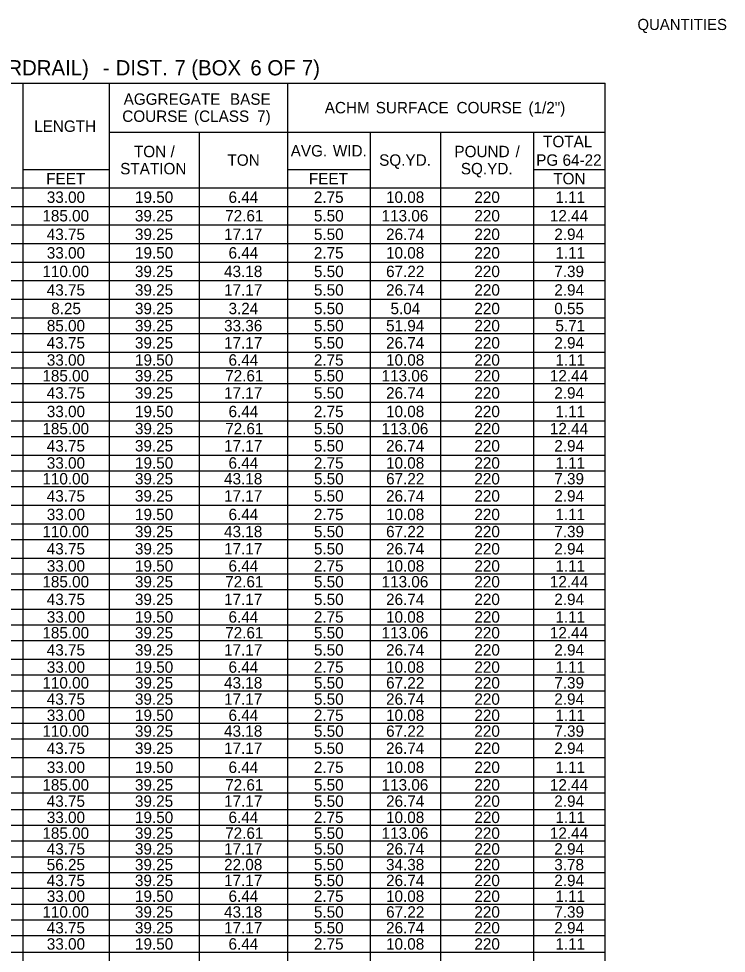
# Model space of a CAD drawing. Extents: x 544250 to 1930787, y -1948365 to 596640.
# Drawn here: x 545339.7 to 545711.4, y -1947838.8 to -1947347.7 of the extents above; entities that cross this region are included whole.
import ezdxf

# ---------------------------------------------------------------- set-up
doc = ezdxf.new("R2010")
doc.units = 0
doc.layers.add('Default', color=7, linetype='Continuous')
doc.layers.add('R_Border Prem', color=7, linetype='Continuous')

msp = doc.modelspace()

# ---------------------------------------------------------------- linework, layer by layer
at = {"layer": 'Default'}
for p, q in [((544964.76, -1947381.48), (545647.75, -1947381.48)), ((545342.09, -1948198.53), (545342.09, -1947381.48)), ((545387.43, -1948198.53), (545387.43, -1947381.48)), ((545481.03, -1948209.26), (545481.03, -1947381.48)), ((545647.75, -1948209.26), (545647.75, -1947381.48)), ((545387.43, -1947407.32), (545647.75, -1947407.32)), ((545434.71, -1948209.26), (545434.71, -1947407.32)), ((545524.41, -1947407.32), (545561.46, -1947407.32)), ((545524.41, -1948209.26), (545524.41, -1947407.32)), ((545561.46, -1948209.26), (545561.46, -1947407.32)), ((545610.21, -1948209.26), (545610.21, -1947407.32)), ((545342.09, -1947426.82), (545387.43, -1947426.82)), ((545387.43, -1947436.57), (545387.43, -1947426.82)), ((545481.03, -1947426.82), (545524.41, -1947426.82)), ((545481.03, -1947436.57), (545481.03, -1947426.82)), ((545524.41, -1947436.57), (545524.41, -1947426.82)), ((545610.21, -1947426.82), (545647.75, -1947426.82)), ((544964.76, -1947436.57), (545647.75, -1947436.57)), ((545387.43, -1947436.57), (545524.41, -1947436.57)), ((545524.41, -1947436.57), (545647.75, -1947436.57)), ((545170.98, -1947446.32), (545647.75, -1947446.32)), ((545170.98, -1947456.07), (545647.75, -1947456.07)), ((545170.98, -1947465.82), (545647.75, -1947465.82)), ((545170.98, -1947475.57), (545647.75, -1947475.57)), ((545170.98, -1947485.32), (545647.75, -1947485.32)), ((545170.98, -1947495.07), (545647.75, -1947495.07)), ((545170.98, -1947504.82), (545647.75, -1947504.82)), ((545170.98, -1947513.11), (545647.75, -1947513.11)), ((545170.98, -1947522.86), (545647.75, -1947522.86)), ((545170.98, -1947531.15), (545647.75, -1947531.15)), ((545170.98, -1947539.43), (545647.75, -1947539.43)), ((544964.76, -1947549.18), (545647.75, -1947549.18)), ((545170.98, -1947558.93), (545647.75, -1947558.93)), ((545170.98, -1947567.22), (545647.75, -1947567.22)), ((545170.98, -1947576.97), (545647.75, -1947576.97)), ((545170.98, -1947585.26), (545647.75, -1947585.26)), ((545170.98, -1947593.55), (545647.75, -1947593.55)), ((545170.98, -1947603.3), (545647.75, -1947603.3)), ((545170.98, -1947613.05), (545647.75, -1947613.05)), ((545170.98, -1947621.33), (545647.75, -1947621.33)), ((545170.98, -1947631.08), (545647.75, -1947631.08)), ((545170.98, -1947639.37), (545647.75, -1947639.37)), ((545170.98, -1947647.66), (545647.75, -1947647.66)), ((544964.76, -1947657.9), (545647.75, -1947657.9)), ((545170.98, -1947666.18), (545647.75, -1947666.18)), ((545170.98, -1947674.47), (545647.75, -1947674.47)), ((545170.98, -1947684.22), (545647.75, -1947684.22)), ((545170.98, -1947692.51), (545647.75, -1947692.51)), ((545170.98, -1947700.8), (545647.75, -1947700.8)), ((545170.98, -1947709.57), (545647.75, -1947709.57)), ((545170.98, -1947717.86), (545647.75, -1947717.86)), ((545170.98, -1947726.15), (545647.75, -1947726.15)), ((545170.98, -1947735.9), (545647.75, -1947735.9)), ((545170.98, -1947746.13), (545647.75, -1947746.13)), ((545170.98, -1947754.42), (545647.75, -1947754.42)), ((544964.76, -1947763.2), (545647.75, -1947763.2)), ((545170.98, -1947771.48), (545647.75, -1947771.48)), ((545170.98, -1947779.77), (545647.75, -1947779.77)), ((545170.98, -1947788.06), (545647.75, -1947788.06)), ((545170.98, -1947796.35), (545647.75, -1947796.35)), ((545170.98, -1947804.63), (545647.75, -1947804.63)), ((545170.98, -1947812.92), (545647.75, -1947812.92)), ((545170.98, -1947821.21), (545647.75, -1947821.21)), ((545170.98, -1947829.5), (545647.75, -1947829.5)), ((545170.98, -1947838.27), (545647.75, -1947838.27))]:
    msp.add_line(p, q, dxfattribs=at)

# ---------------------------------------------------------------- texts
for s, height, p in [(' GUARDRAIL)', 8, (545307.6, -1947377.44)), (' DIST.', 8, (545387.66, -1947377.44)), (' 7', 8, (545418.56, -1947377.44)), (' (BOX', 8, (545427.38, -1947377.44)), (' 6', 8, (545458.42, -1947377.44)), (' OF', 8, (545467.34, -1947377.44)), (' 7)', 8, (545485.45, -1947377.44)), (' -', 8, (545380.91, -1947377.44)), ('AGGREGATE', 6, (545394.81, -1947392.9)), (' BASE', 6, (545448.43, -1947392.9)), ('ACHM', 6, (545500.45, -1947397.4)), (' SURFACE', 6, (545525, -1947397.4)), (' COURSE', 6, (545567.44, -1947397.4)), (' (1/2")', 6, (545605.23, -1947397.4)), ('COURSE', 6, (545394.1, -1947401.9)), (' (CLASS', 6, (545429.56, -1947401.9)), (' 7)', 6, (545462.68, -1947401.9)), ('LENGTH', 6, (545347.84, -1947407.15)), ('TOTAL', 6, (545615.14, -1947415.2)), ('TON', 6, (545400.22, -1947420.45)), (' /', 6, (545417.25, -1947420.45)), ('AVG.', 6, (545482.57, -1947420.07)), (' WID.', 6, (545502.49, -1947420.07)), ('POUND', 6, (545568.57, -1947420.45)), (' /', 6, (545598.44, -1947420.45)), ('TON', 6, (545449.36, -1947424.95)), ('SQ.YD.', 6, (545529.02, -1947424.95)), ('PG', 6, (545611.51, -1947424.95)), (' 64-22', 6, (545623.12, -1947424.95)), ('STATION', 6, (545393.01, -1947429.45)), ('SQ.YD.', 6, (545571.92, -1947429.45)), ('FEET', 6, (545354.13, -1947434.7)), ('FEET', 6, (545492.09, -1947434.7)), ('TON', 6, (545620.47, -1947434.7)), ('33.00', 6, (545354.47, -1947444.45)), ('19.50', 6, (545400.79, -1947444.45)), ('6.44', 6, (545449.92, -1947444.45)), ('2.75', 6, (545494.73, -1947444.45)), ('10.08', 6, (545532.64, -1947444.45)), ('220', 6, (545579.05, -1947444.45)), ('1.11', 6, (545621.6, -1947444.45)), ('185.00', 6, (545352.14, -1947454.2)), ('39.25', 6, (545400.75, -1947454.2)), ('72.61', 6, (545448.16, -1947454.2)), ('5.50', 6, (545494.77, -1947454.2)), ('113.06', 6, (545530.31, -1947454.2)), ('220', 6, (545579.05, -1947454.2)), ('12.44', 6, (545618.7, -1947454.2)), ('43.75', 6, (545354.44, -1947463.95)), ('39.25', 6, (545400.75, -1947463.95)), ('17.17', 6, (545447.57, -1947463.95)), ('5.50', 6, (545494.77, -1947463.95)), ('26.74', 6, (545532.66, -1947463.95)), ('220', 6, (545579.05, -1947463.95)), ('2.94', 6, (545621.03, -1947463.95)), ('33.00', 6, (545354.47, -1947473.7)), ('19.50', 6, (545400.79, -1947473.7)), ('6.44', 6, (545449.92, -1947473.7)), ('2.75', 6, (545494.73, -1947473.7)), ('10.08', 6, (545532.64, -1947473.7)), ('220', 6, (545579.05, -1947473.7)), ('1.11', 6, (545621.6, -1947473.7)), ('110.00', 6, (545352.14, -1947483.45)), ('39.25', 6, (545400.75, -1947483.45)), ('43.18', 6, (545447.57, -1947483.45)), ('5.50', 6, (545494.77, -1947483.45)), ('67.22', 6, (545532.68, -1947483.45)), ('220', 6, (545579.05, -1947483.45)), ('7.39', 6, (545621.01, -1947483.45)), ('43.75', 6, (545354.44, -1947493.2)), ('39.25', 6, (545400.75, -1947493.2)), ('17.17', 6, (545447.57, -1947493.2)), ('5.50', 6, (545494.77, -1947493.2)), ('26.74', 6, (545532.66, -1947493.2)), ('220', 6, (545579.05, -1947493.2)), ('2.94', 6, (545621.03, -1947493.2)), ('8.25', 6, (545356.77, -1947502.95)), ('39.25', 6, (545400.75, -1947502.95)), ('3.24', 6, (545449.92, -1947502.95)), ('5.50', 6, (545494.77, -1947502.95)), ('5.04', 6, (545534.99, -1947502.95)), ('220', 6, (545579.05, -1947502.95)), ('0.55', 6, (545620.99, -1947502.95)), ('85.00', 6, (545354.47, -1947511.97)), ('39.25', 6, (545400.75, -1947511.97)), ('33.36', 6, (545447.57, -1947511.97)), ('5.50', 6, (545494.77, -1947511.97)), ('51.94', 6, (545532.66, -1947511.97)), ('220', 6, (545579.05, -1947511.97)), ('5.71', 6, (545621.6, -1947511.97)), ('43.75', 6, (545354.44, -1947520.98)), ('39.25', 6, (545400.75, -1947520.98)), ('17.17', 6, (545447.57, -1947520.98)), ('5.50', 6, (545494.77, -1947520.98)), ('26.74', 6, (545532.66, -1947520.98)), ('220', 6, (545579.05, -1947520.98)), ('2.94', 6, (545621.03, -1947520.98)), ('33.00', 6, (545354.47, -1947530)), ('19.50', 6, (545400.79, -1947530)), ('6.44', 6, (545449.92, -1947530)), ('2.75', 6, (545494.73, -1947530)), ('10.08', 6, (545532.64, -1947530)), ('220', 6, (545579.05, -1947530)), ('1.11', 6, (545621.6, -1947530)), ('185.00', 6, (545352.14, -1947538.29)), ('39.25', 6, (545400.75, -1947538.29)), ('72.61', 6, (545448.16, -1947538.29)), ('5.50', 6, (545494.77, -1947538.29)), ('113.06', 6, (545530.31, -1947538.29)), ('220', 6, (545579.05, -1947538.29)), ('12.44', 6, (545618.7, -1947538.29)), ('43.75', 6, (545354.44, -1947547.31)), ('39.25', 6, (545400.75, -1947547.31)), ('17.17', 6, (545447.57, -1947547.31)), ('5.50', 6, (545494.77, -1947547.31)), ('26.74', 6, (545532.66, -1947547.31)), ('220', 6, (545579.05, -1947547.31)), ('2.94', 6, (545621.03, -1947547.31)), ('33.00', 6, (545354.47, -1947557.06)), ('19.50', 6, (545400.79, -1947557.06)), ('6.44', 6, (545449.92, -1947557.06)), ('2.75', 6, (545494.73, -1947557.06)), ('10.08', 6, (545532.64, -1947557.06)), ('220', 6, (545579.05, -1947557.06)), ('1.11', 6, (545621.6, -1947557.06)), ('185.00', 6, (545352.14, -1947566.08)), ('39.25', 6, (545400.75, -1947566.08)), ('72.61', 6, (545448.16, -1947566.08)), ('5.50', 6, (545494.77, -1947566.08)), ('113.06', 6, (545530.31, -1947566.08)), ('220', 6, (545579.05, -1947566.08)), ('12.44', 6, (545618.7, -1947566.08)), ('43.75', 6, (545354.44, -1947575.1)), ('39.25', 6, (545400.75, -1947575.1)), ('17.17', 6, (545447.57, -1947575.1)), ('5.50', 6, (545494.77, -1947575.1)), ('26.74', 6, (545532.66, -1947575.1)), ('220', 6, (545579.05, -1947575.1)), ('2.94', 6, (545621.03, -1947575.1)), ('33.00', 6, (545354.47, -1947584.12)), ('19.50', 6, (545400.79, -1947584.12)), ('6.44', 6, (545449.92, -1947584.12)), ('2.75', 6, (545494.73, -1947584.12)), ('10.08', 6, (545532.64, -1947584.12)), ('220', 6, (545579.05, -1947584.12)), ('1.11', 6, (545621.6, -1947584.12)), ('110.00', 6, (545352.14, -1947592.4)), ('39.25', 6, (545400.75, -1947592.4)), ('43.18', 6, (545447.57, -1947592.4)), ('5.50', 6, (545494.77, -1947592.4)), ('67.22', 6, (545532.68, -1947592.4)), ('220', 6, (545579.05, -1947592.4)), ('7.39', 6, (545621.01, -1947592.4)), ('43.75', 6, (545354.44, -1947601.42)), ('39.25', 6, (545400.75, -1947601.42)), ('17.17', 6, (545447.57, -1947601.42)), ('5.50', 6, (545494.77, -1947601.42)), ('26.74', 6, (545532.66, -1947601.42)), ('220', 6, (545579.05, -1947601.42)), ('2.94', 6, (545621.03, -1947601.42)), ('33.00', 6, (545354.47, -1947611.17)), ('19.50', 6, (545400.79, -1947611.17)), ('6.44', 6, (545449.92, -1947611.17)), ('2.75', 6, (545494.73, -1947611.17)), ('10.08', 6, (545532.64, -1947611.17)), ('220', 6, (545579.05, -1947611.17)), ('1.11', 6, (545621.6, -1947611.17)), ('110.00', 6, (545352.14, -1947620.19)), ('39.25', 6, (545400.75, -1947620.19)), ('43.18', 6, (545447.57, -1947620.19)), ('5.50', 6, (545494.77, -1947620.19)), ('67.22', 6, (545532.68, -1947620.19)), ('220', 6, (545579.05, -1947620.19)), ('7.39', 6, (545621.01, -1947620.19)), ('43.75', 6, (545354.44, -1947629.21)), ('39.25', 6, (545400.75, -1947629.21)), ('17.17', 6, (545447.57, -1947629.21)), ('5.50', 6, (545494.77, -1947629.21)), ('26.74', 6, (545532.66, -1947629.21)), ('220', 6, (545579.05, -1947629.21)), ('2.94', 6, (545621.03, -1947629.21)), ('33.00', 6, (545354.47, -1947638.23)), ('19.50', 6, (545400.79, -1947638.23)), ('6.44', 6, (545449.92, -1947638.23)), ('2.75', 6, (545494.73, -1947638.23)), ('10.08', 6, (545532.64, -1947638.23)), ('220', 6, (545579.05, -1947638.23)), ('1.11', 6, (545621.6, -1947638.23)), ('185.00', 6, (545352.14, -1947646.52)), ('39.25', 6, (545400.75, -1947646.52)), ('72.61', 6, (545448.16, -1947646.52)), ('5.50', 6, (545494.77, -1947646.52)), ('113.06', 6, (545530.31, -1947646.52)), ('220', 6, (545579.05, -1947646.52)), ('12.44', 6, (545618.7, -1947646.52)), ('43.75', 6, (545354.44, -1947655.78)), ('39.25', 6, (545400.75, -1947655.78)), ('17.17', 6, (545447.57, -1947655.78)), ('5.50', 6, (545494.77, -1947655.78)), ('26.74', 6, (545532.66, -1947655.78)), ('220', 6, (545579.05, -1947655.78)), ('2.94', 6, (545621.03, -1947655.78)), ('33.00', 6, (545354.47, -1947665.04)), ('19.50', 6, (545400.79, -1947665.04)), ('6.44', 6, (545449.92, -1947665.04)), ('2.75', 6, (545494.73, -1947665.04)), ('10.08', 6, (545532.64, -1947665.04)), ('220', 6, (545579.05, -1947665.04)), ('1.11', 6, (545621.6, -1947665.04)), ('185.00', 6, (545352.14, -1947673.33)), ('39.25', 6, (545400.75, -1947673.33)), ('72.61', 6, (545448.16, -1947673.33)), ('5.50', 6, (545494.77, -1947673.33)), ('113.06', 6, (545530.31, -1947673.33)), ('220', 6, (545579.05, -1947673.33)), ('12.44', 6, (545618.7, -1947673.33)), ('43.75', 6, (545354.44, -1947682.35)), ('39.25', 6, (545400.75, -1947682.35)), ('17.17', 6, (545447.57, -1947682.35)), ('5.50', 6, (545494.77, -1947682.35)), ('26.74', 6, (545532.66, -1947682.35)), ('220', 6, (545579.05, -1947682.35)), ('2.94', 6, (545621.03, -1947682.35)), ('33.00', 6, (545354.47, -1947691.37)), ('19.50', 6, (545400.79, -1947691.37)), ('6.44', 6, (545449.92, -1947691.37)), ('2.75', 6, (545494.73, -1947691.37)), ('10.08', 6, (545532.64, -1947691.37)), ('220', 6, (545579.05, -1947691.37)), ('1.11', 6, (545621.6, -1947691.37)), ('110.00', 6, (545352.14, -1947699.65)), ('39.25', 6, (545400.75, -1947699.65)), ('43.18', 6, (545447.57, -1947699.65)), ('5.50', 6, (545494.77, -1947699.65)), ('67.22', 6, (545532.68, -1947699.65)), ('220', 6, (545579.05, -1947699.65)), ('7.39', 6, (545621.01, -1947699.65)), ('43.75', 6, (545354.44, -1947708.18)), ('39.25', 6, (545400.75, -1947708.18)), ('5.50', 6, (545494.77, -1947708.18)), ('26.74', 6, (545532.66, -1947708.18)), ('220', 6, (545579.05, -1947708.18)), ('2.94', 6, (545621.03, -1947708.18)), ('17.17', 6, (545447.57, -1947708.18)), ('33.00', 6, (545354.47, -1947716.72)), ('19.50', 6, (545400.79, -1947716.72)), ('6.44', 6, (545449.92, -1947716.72)), ('2.75', 6, (545494.73, -1947716.72)), ('10.08', 6, (545532.64, -1947716.72)), ('220', 6, (545579.05, -1947716.72)), ('1.11', 6, (545621.6, -1947716.72)), ('110.00', 6, (545352.14, -1947725)), ('39.25', 6, (545400.75, -1947725)), ('43.18', 6, (545447.57, -1947725)), ('5.50', 6, (545494.77, -1947725)), ('67.22', 6, (545532.68, -1947725)), ('220', 6, (545579.05, -1947725)), ('7.39', 6, (545621.01, -1947725)), ('43.75', 6, (545354.44, -1947734.02)), ('39.25', 6, (545400.75, -1947734.02)), ('17.17', 6, (545447.57, -1947734.02)), ('5.50', 6, (545494.77, -1947734.02)), ('26.74', 6, (545532.66, -1947734.02)), ('220', 6, (545579.05, -1947734.02)), ('2.94', 6, (545621.03, -1947734.02)), ('33.00', 6, (545354.47, -1947744.02)), ('19.50', 6, (545400.79, -1947744.02)), ('6.44', 6, (545449.92, -1947744.02)), ('2.75', 6, (545494.73, -1947744.02)), ('10.08', 6, (545532.64, -1947744.02)), ('220', 6, (545579.05, -1947744.02)), ('1.11', 6, (545621.6, -1947744.02)), ('185.00', 6, (545352.14, -1947753.28)), ('39.25', 6, (545400.75, -1947753.28)), ('72.61', 6, (545448.16, -1947753.28)), ('5.50', 6, (545494.77, -1947753.28)), ('113.06', 6, (545530.31, -1947753.28)), ('220', 6, (545579.05, -1947753.28)), ('12.44', 6, (545618.7, -1947753.28)), ('43.75', 6, (545354.44, -1947761.81)), ('39.25', 6, (545400.75, -1947761.81)), ('17.17', 6, (545447.57, -1947761.81)), ('5.50', 6, (545494.77, -1947761.81)), ('26.74', 6, (545532.66, -1947761.81)), ('220', 6, (545579.05, -1947761.81)), ('2.94', 6, (545621.03, -1947761.81)), ('33.00', 6, (545354.47, -1947770.34)), ('19.50', 6, (545400.79, -1947770.34)), ('6.44', 6, (545449.92, -1947770.34)), ('2.75', 6, (545494.73, -1947770.34)), ('10.08', 6, (545532.64, -1947770.34)), ('220', 6, (545579.05, -1947770.34)), ('1.11', 6, (545621.6, -1947770.34)), ('185.00', 6, (545352.14, -1947778.63)), ('39.25', 6, (545400.75, -1947778.63)), ('72.61', 6, (545448.16, -1947778.63)), ('5.50', 6, (545494.77, -1947778.63)), ('113.06', 6, (545530.31, -1947778.63)), ('220', 6, (545579.05, -1947778.63)), ('12.44', 6, (545618.7, -1947778.63)), ('43.75', 6, (545354.44, -1947786.92)), ('39.25', 6, (545400.75, -1947786.92)), ('17.17', 6, (545447.57, -1947786.92)), ('5.50', 6, (545494.77, -1947786.92)), ('26.74', 6, (545532.66, -1947786.92)), ('220', 6, (545579.05, -1947786.92)), ('2.94', 6, (545621.03, -1947786.92)), ('56.25', 6, (545354.44, -1947795.2)), ('39.25', 6, (545400.75, -1947795.2)), ('22.08', 6, (545447.57, -1947795.2)), ('5.50', 6, (545494.77, -1947795.2)), ('34.38', 6, (545532.64, -1947795.2)), ('220', 6, (545579.05, -1947795.2)), ('3.78', 6, (545621.01, -1947795.2)), ('43.75', 6, (545354.44, -1947803.49)), ('39.25', 6, (545400.75, -1947803.49)), ('17.17', 6, (545447.57, -1947803.49)), ('5.50', 6, (545494.77, -1947803.49)), ('26.74', 6, (545532.66, -1947803.49)), ('220', 6, (545579.05, -1947803.49)), ('2.94', 6, (545621.03, -1947803.49)), ('33.00', 6, (545354.47, -1947811.78)), ('19.50', 6, (545400.79, -1947811.78)), ('6.44', 6, (545449.92, -1947811.78)), ('2.75', 6, (545494.73, -1947811.78)), ('10.08', 6, (545532.64, -1947811.78)), ('220', 6, (545579.05, -1947811.78)), ('1.11', 6, (545621.6, -1947811.78)), ('110.00', 6, (545352.14, -1947820.07)), ('39.25', 6, (545400.75, -1947820.07)), ('43.18', 6, (545447.57, -1947820.07)), ('5.50', 6, (545494.77, -1947820.07)), ('67.22', 6, (545532.68, -1947820.07)), ('220', 6, (545579.05, -1947820.07)), ('7.39', 6, (545621.01, -1947820.07)), ('43.75', 6, (545354.44, -1947828.35)), ('39.25', 6, (545400.75, -1947828.35)), ('17.17', 6, (545447.57, -1947828.35)), ('5.50', 6, (545494.77, -1947828.35)), ('26.74', 6, (545532.66, -1947828.35)), ('220', 6, (545579.05, -1947828.35)), ('2.94', 6, (545621.03, -1947828.35)), ('33.00', 6, (545354.47, -1947836.88)), ('19.50', 6, (545400.79, -1947836.88)), ('6.44', 6, (545449.92, -1947836.88)), ('2.75', 6, (545494.73, -1947836.88)), ('10.08', 6, (545532.64, -1947836.88)), ('220', 6, (545579.05, -1947836.88)), ('1.11', 6, (545621.6, -1947836.88))]:
    msp.add_text(s, height=height, dxfattribs=at).set_placement(p)
at = {"layer": 'R_Border Prem'}
msp.add_text('QUANTITIES', height=5.862, rotation=360, dxfattribs=at).set_placement((545664.68, -1947353.61))

doc.saveas('drawing.dxf')
